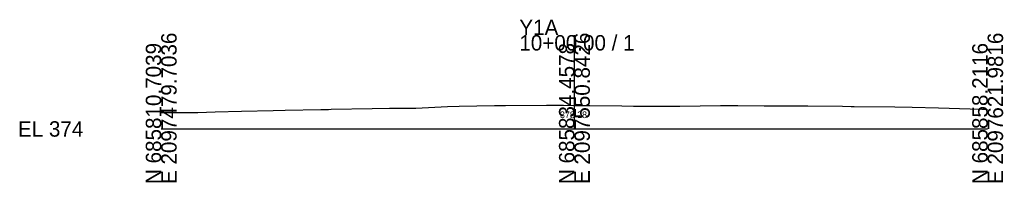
# Model space of a CAD drawing. Extents: x -769 to 2415, y -10 to 2028.
# Drawn here: x -769.3 to -590.8, y -9.7 to 19.8 of the extents above; entities that cross this region are included whole.
import ezdxf

# ---------------------------------------------------------------- set-up
doc = ezdxf.new("R2010")
doc.units = 0
for name, color, linetype in [('Exist Cross Section Cell', 7, 'Continuous'), ('Exist XS Center Line Elevation Label', 7, 'Continuous'), ('Exist XS Ground Line', 7, 'Continuous')]:
    doc.layers.add(name, color=color, linetype=linetype)

msp = doc.modelspace()

# ---------------------------------------------------------------- linework, layer by layer
at = {"layer": 'Exist Cross Section Cell'}
for p, q in [((-668.64, 0), (-668.64, 17.04)), ((-743.64, 0), (-668.64, 0)), ((-668.64, 0), (-593.64, 0))]:
    msp.add_line(p, q, dxfattribs=at)
at = {"layer": 'Exist XS Ground Line'}
msp.add_lwpolyline([(-743.64, 2.96), (-736.97, 2.99), (-733.86, 3.13), (-729.06, 3.2), (-723.32, 3.34), (-721.16, 3.43), (-714.69, 3.53), (-713.25, 3.56), (-712.77, 3.57), (-705.35, 3.73), (-702.23, 3.75), (-697.45, 3.79), (-691.69, 4.08), (-689.54, 4.16), (-683.12, 4.26), (-681.64, 4.26), (-681.14, 4.28), (-673.73, 4.29), (-670.6, 4.3), (-668.64, 4.28), (-665.83, 4.24), (-660.05, 4.18), (-657.92, 4.16), (-651.54, 4.15), (-650.02, 4.14), (-649.51, 4.15), (-642.11, 4.23), (-638.97, 4.24), (-634.21, 4.17), (-628.42, 4.2), (-626.3, 4.19), (-619.96, 4.12), (-618.4, 4.09), (-617.88, 4.08), (-610.5, 4.04), (-607.33, 3.98), (-602.59, 3.84), (-596.79, 3.66), (-594.69, 3.6), (-593.64, 3.54)], dxfattribs=at)

# ---------------------------------------------------------------- texts
at = {"layer": 'Exist Cross Section Cell'}
for s, p in [('Y1A', (-678.64, 17.04)), ('10+00.00 / 1', (-678.64, 14.24)), ('EL 374', (-769.64, -1.4))]:
    msp.add_text(s, height=2.8, dxfattribs=at).set_placement(p)
for s, p in [('E 2097479.7036', (-740.84, -10)), ('E 2097550.8426', (-665.84, -10)), ('E 2097621.9816', (-590.84, -10)), ('N 685810.7039', (-743.64, -10)), ('N 685834.4578', (-668.64, -10)), ('N 685858.2116', (-593.64, -10))]:
    msp.add_text(s, height=2.8, rotation=90, dxfattribs=at).set_placement(p)
at = {"layer": 'Exist XS Center Line Elevation Label'}
msp.add_text('378.28', height=1.2, dxfattribs=at).set_placement((-671.26, 1.97))

doc.saveas('drawing.dxf')
